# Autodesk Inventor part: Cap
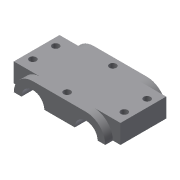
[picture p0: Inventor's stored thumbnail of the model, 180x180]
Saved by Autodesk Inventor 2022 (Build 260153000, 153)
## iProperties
Created: 2002-02
Part Number: Cap
Document SubType Name: Modeling
Designer: ***
Density: 1 g/cm^3
Material: Generic
Appearance: Default
Control State: 0
Master: False
Checked Out: False
Shininess: 77.0
Length Units: 11269
Angle Units: 11279
Time Units: 11290
Mass Units: 11283
Length Display Precision: 3
Angle Display Precision: 2
Density: 0.0
Volumn: 0.0
Area: 0.0
PropertySet Name: Model Information
Author: ***
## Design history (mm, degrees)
sketch "Sketch2"
  geometry: L1 (-17.5, 12.5)-(17.5, 12.5); L2 (30, 0)-(25, 0); L3 (10, 0)-(-10, 0); L4 (-25, 0)-(-30, 0); A1 r 12.5 centre (-17.5, 0) between (-17.5, 12.5) and (-30, 0); A2 r 12.5 centre (17.5, 0) between (30, 0) and (17.5, 12.5); A3 r 7.5 centre (17.5, 0) between (25, 0) and (10, 0); A4 r 7.5 centre (-17.5, 0) between (-10, 0) and (-25, 0)
  constraints: 8 end point, 8 point on circle, 4 centre point, 3 horizontal, 3 parallel, 2 coincident, 2 equal radius, 2 tangent
  dimensions: "d0" = 12.5 radius of A1; "d1" = 7.5 radius of A4; "d2" = 35 distance of A1.centre A2.centre; "d3" = 12.5 distance between parallel lines of L1 L3
extrude "Extrusion1" new body sketch "Sketch2" stored distance "d4" = 40; taper "d5" = 0 deg
workplane "Work Plane1"
sketch "Sketch3"
  geometry: L1 (-15, 12.5)-(15, 12.5); L2 (15, 12.5)-(15, 0); L3 (15, 0)-(-15, 0); L4 (-15, 0)-(-15, 12.5); L5 (-20, 0)-(20, 0) reference; L6 (-20, 12.5)-(20, 12.5) reference; L7 (20, 12.5)-(20, 0) reference
  constraints: 8 end point, 2 collinear, 2 parallel, 1 horizontal, 1 perpendicular
  dimensions: "d7" = 30 distance of L2.end L3.end; "d8" = 5 distance between parallel lines of L7 L2
extrude "Extrusion2" join sketch "Sketch3" stored distance "d9" = 40; taper "d10" = 0 deg
mirror "Mirror1"
sketch "Sketch4"
  geometry: L1 (-17.5, -35)-(0, -35) reference; L2 (-17.5, -35)-(-17.5, -5) reference; 1 further point
  dimensions: "d12" = 7.5 distance from line of L1 point (-12.5, -27.5); "d13" = 5 distance from line of L2 point (-12.5, -27.5)
hole "Hole1" sketch "Sketch4" at (-12.5, -27.5) diameter "d14" = 4.5; stored, may be unused: countersink angle "d18" = 82 deg, drill point angle "d20" = 118 deg; dims "d15" = 6, "d16" = 4, "d17" = 2, "d19" = 8
pattern_linear "Rectangular Pattern1" dims "d23" = 60, "d26" = 15
sketch "Sketch5"
  geometry: L1 (0, -40)-(35, -40) reference; L2 (-17.5, -35)-(-17.5, -5) reference; 1 further point
  dimensions: "d27" = 5 distance from line of L1 point (17.5, -35); "d28" = 35 distance from line of L2 point (17.5, -35)
hole "Hole2" sketch "Sketch5" at (17.5, -35) diameter "d29" = 4.5; stored, may be unused: countersink angle "d33" = 82 deg, drill point angle "d35" = 118 deg; dims "d30" = 6, "d31" = 4, "d32" = 2, "d34" = 8
pattern_linear "Rectangular Pattern2" dims "d38" = 30
body "Solid1"
other parameters: "d11" = 35
